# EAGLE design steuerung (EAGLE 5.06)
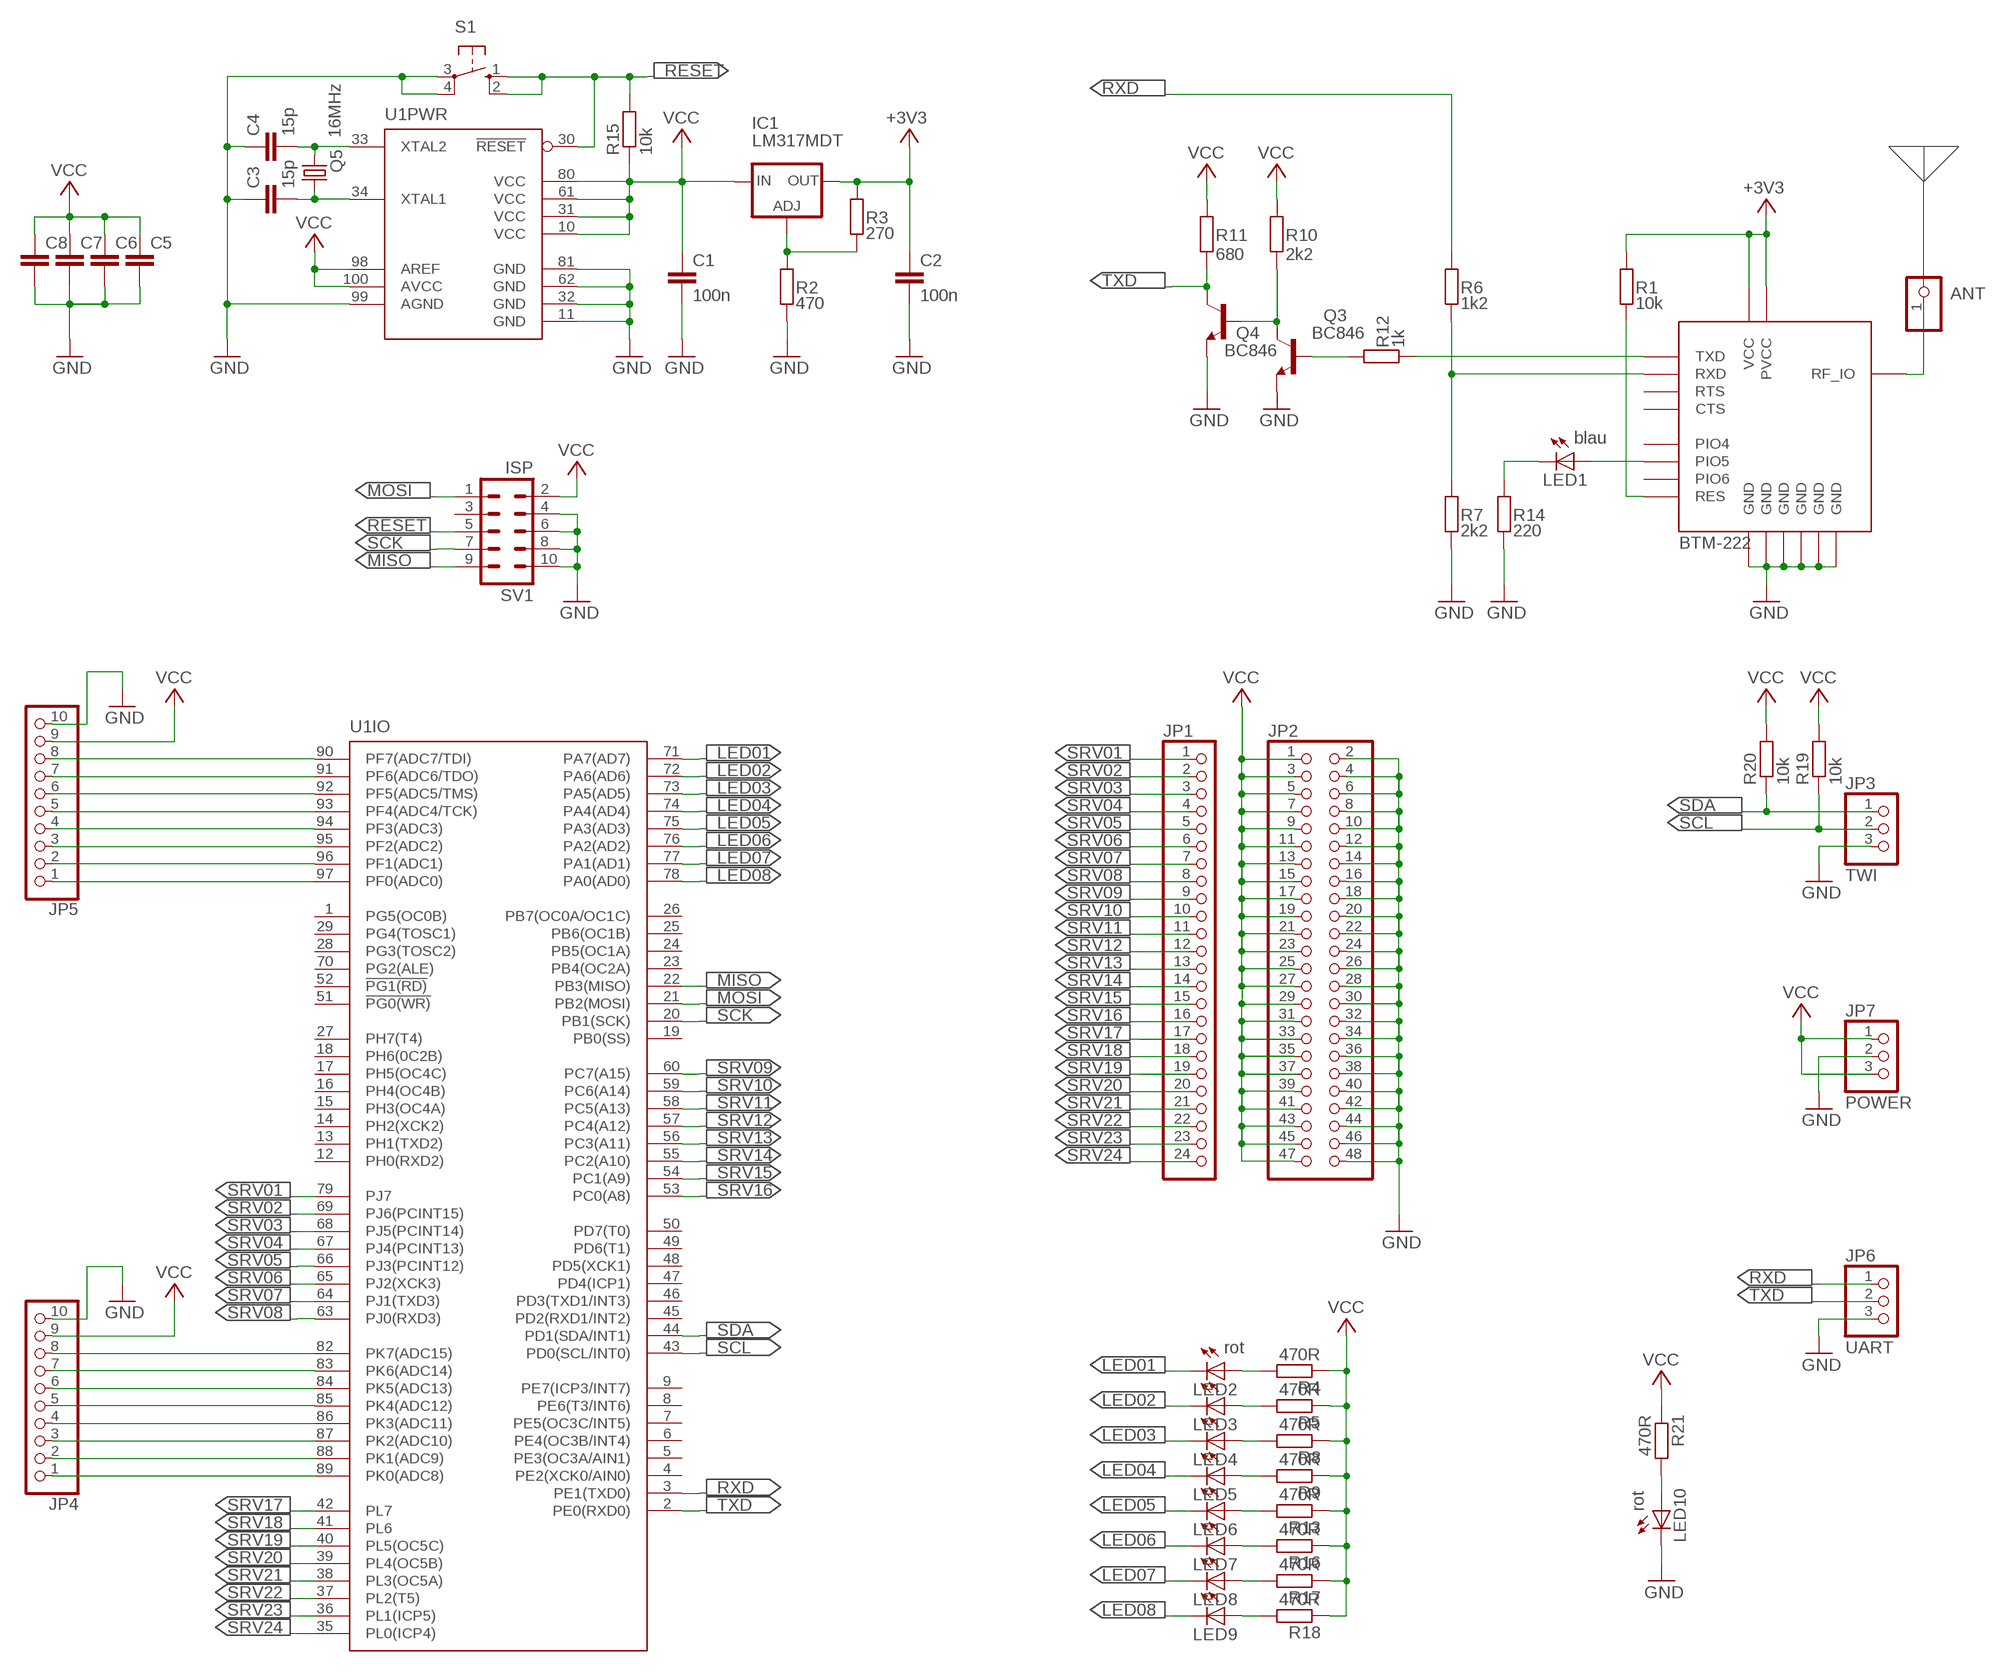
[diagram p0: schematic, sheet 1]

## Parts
ANT  PINHD-1X1  [1X01]
C1  100n  C-EUC0805  [C0805]
C2  100n  C-EUC0805  [C0805]
C3  15p  C-EUC0805  [C0805]
C4  15p  C-EUC0805  [C0805]
C5  C-EUC0805  [C0805]
C6  C-EUC0805  [C0805]
C7  C-EUC0805  [C0805]
C8  C-EUC0805  [C0805]
IC1  LM317MDT  [DPACK]
IC4  BTM_SER  [BTM_222]
JP1  PINHD-1X24  [1X24]
JP2  PINHD-2X24  [2X24]
JP3  TWI  PINHD-1X3  [1X03]
JP4  PINHD-1X10  [1X10]
JP5  PINHD-1X10  [1X10]
JP6  UART  PINHD-1X3  [1X03]
JP7  POWER  PINHD-1X3  [1X03]
LED1  LEDCHIP-LED0805  [CHIP-LED0805]
LED2  LEDCHIP-LED0805  [CHIP-LED0805]
LED3  LEDCHIP-LED0805  [CHIP-LED0805]
LED4  LEDCHIP-LED0805  [CHIP-LED0805]
LED5  LEDCHIP-LED0805  [CHIP-LED0805]
LED6  LEDCHIP-LED0805  [CHIP-LED0805]
LED7  LEDCHIP-LED0805  [CHIP-LED0805]
LED8  LEDCHIP-LED0805  [CHIP-LED0805]
LED9  LEDCHIP-LED0805  [CHIP-LED0805]
LED10  LEDCHIP-LED0805  [CHIP-LED0805]
Q3  BC846  BC846ALT1SMD  [SOT23]
Q4  BC846  BC846ALT1SMD  [SOT23]
Q5  16MHz  CRYSTALHC49U-V  [HC49U-V]
R1  10k  R-EU_M0805  [M0805]
R2  470  R-EU_M0805  [M0805]
R3  270  R-EU_M0805  [M0805]
R4  470R  R-EU_M0805  [M0805]
R5  470R  R-EU_M0805  [M0805]
R6  1k2  R-EU_M0805  [M0805]
R7  2k2  R-EU_M0805  [M0805]
R8  470R  R-EU_M0805  [M0805]
R9  470R  R-EU_M0805  [M0805]
R10  2k2  R-EU_M0805  [M0805]
R11  680  R-EU_M0805  [M0805]
R12  1k  R-EU_M0805  [M0805]
R13  470R  R-EU_M0805  [M0805]
R14  220  R-EU_M0805  [M0805]
R15  10k  R-EU_M0805  [M0805]
R16  470R  R-EU_M0805  [M0805]
R17  470R  R-EU_M0805  [M0805]
R18  470R  R-EU_M0805  [M0805]
R19  10k  R-EU_M0805  [M0805]
R20  10k  R-EU_M0805  [M0805]
R21  470R  R-EU_M0805  [M0805]
S1  10-XX  [B3F-10XX]
SV1  ISP  ML10  [ML10]
U1  ATMEGA640  [TQFP100]

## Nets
+3V3: C2.1 IC1.4(OUT) IC4.P$2(PVCC) IC4.P$17(VCC) R1.2 R3.2
GND: C1.2 C2.2 C3.1 C4.1 C5.2 C6.2 C7.2 C8.2 IC4.P$1(GND) IC4.P$10(GND) IC4.P$18(GND) IC4.P$19(GND) IC4.P$29(GND) IC4.P$38(GND) JP2.2 JP2.4 JP2.6 JP2.8 JP2.10 JP2.12 JP2.14 JP2.16 JP2.18 JP2.20 JP2.22 JP2.24 JP2.26 JP2.28 JP2.30 JP2.32 JP2.34 JP2.36 JP2.38 JP2.40 JP2.42 JP2.44 JP2.46 JP2.48 JP3.3 JP4.10 JP5.10 JP6.3 JP7.2 LED10.C Q3.2(E) Q4.2(E) R2.1 R7.1 R14.1 S1.3(P) S1.4(P1) SV1.4 SV1.6 SV1.8 SV1.10 U1.11(PWR:GND) U1.32(PWR:GND) U1.62(PWR:GND) U1.81(PWR:GND) U1.99(PWR:AGND)
LED01: LED2.C U1.71(IO:PA7(AD7))
LED02: LED3.C U1.72(IO:PA6(AD6))
LED03: LED4.C U1.73(IO:PA5(AD5))
LED04: LED5.C U1.74(IO:PA4(AD4))
LED05: LED6.C U1.75(IO:PA3(AD3))
LED06: LED7.C U1.76(IO:PA2(AD2))
LED07: LED8.C U1.77(IO:PA1(AD1))
LED08: LED9.C U1.78(IO:PA0(AD0))
MISO: SV1.9 U1.22(IO:PB3(MISO))
MOSI: SV1.1 U1.21(IO:PB2(MOSI))
N$1: LED2.A R4.2
N$2: IC1.1(ADJ) R2.2 R3.1
N$3: IC4.P$27(TXD) R12.1
N$4: LED3.A R5.2
N$5: IC4.P$26(RXD) R6.1 R7.2
N$6: ANT.1 IC4.P$37(RF_IO)
N$7: C3.2 Q5.1 U1.34(PWR:XTAL1)
N$8: LED4.A R8.2
N$9: Q3.3(C) Q4.1(B) R10.2
N$10: IC4.P$11(PIO5) LED1.A
N$11: LED5.A R9.2
N$12: Q3.1(B) R12.2
N$13: LED1.C R14.2
N$14: LED6.A R13.2
N$15: C4.2 Q5.2 U1.33(PWR:XTAL2)
N$16: LED7.A R16.2
N$17: LED8.A R17.2
N$18: LED9.A R18.2
N$19: JP5.1 U1.97(IO:PF0(ADC0))
N$20: JP5.2 U1.96(IO:PF1(ADC1))
N$21: JP5.3 U1.95(IO:PF2(ADC2))
N$22: JP5.4 U1.94(IO:PF3(ADC3))
N$23: IC4.P$16(RES) R1.1
N$24: JP5.5 U1.93(IO:PF4(ADC4/TCK))
N$25: JP5.6 U1.92(IO:PF5(ADC5/TMS))
N$26: JP5.7 U1.91(IO:PF6(ADC6/TDO))
N$27: JP5.8 U1.90(IO:PF7(ADC7/TDI))
N$28: JP4.1 U1.89(IO:PK0(ADC8))
N$29: JP4.2 U1.88(IO:PK1(ADC9))
N$30: JP4.3 U1.87(IO:PK2(ADC10))
N$31: JP4.4 U1.86(IO:PK3(ADC11))
N$32: JP4.5 U1.85(IO:PK4(ADC12))
N$33: JP4.6 U1.84(IO:PK5(ADC13))
N$34: JP4.7 U1.83(IO:PK6(ADC14))
N$35: JP4.8 U1.82(IO:PK7(ADC15))
N$36: LED10.A R21.2
RESET: R15.2 S1.1(S) S1.2(S1) SV1.5 U1.30(PWR:!RESET)
RXD: JP6.1 R6.2 U1.3(IO:PE1(TXD0))
SCK: SV1.7 U1.20(IO:PB1(SCK))
SCL: JP3.2 R19.1 U1.43(IO:PD0(SCL/INT0))
SDA: JP3.1 R20.1 U1.44(IO:PD1(SDA/INT1))
SRV01: JP1.1 U1.79(IO:PJ7)
SRV02: JP1.2 U1.69(IO:PJ6(PCINT15))
SRV03: JP1.3 U1.68(IO:PJ5(PCINT14))
SRV04: JP1.4 U1.67(IO:PJ4(PCINT13))
SRV05: JP1.5 U1.66(IO:PJ3(PCINT12))
SRV06: JP1.6 U1.65(IO:PJ2(XCK3))
SRV07: JP1.7 U1.64(IO:PJ1(TXD3))
SRV08: JP1.8 U1.63(IO:PJ0(RXD3))
SRV09: JP1.9 U1.60(IO:PC7(A15))
SRV10: JP1.10 U1.59(IO:PC6(A14))
SRV11: JP1.11 U1.58(IO:PC5(A13))
SRV12: JP1.12 U1.57(IO:PC4(A12))
SRV13: JP1.13 U1.56(IO:PC3(A11))
SRV14: JP1.14 U1.55(IO:PC2(A10))
SRV15: JP1.15 U1.54(IO:PC1(A9))
SRV16: JP1.16 U1.53(IO:PC0(A8))
SRV17: JP1.17 U1.42(IO:PL7)
SRV18: JP1.18 U1.41(IO:PL6)
SRV19: JP1.19 U1.40(IO:PL5(OC5C))
SRV20: JP1.20 U1.39(IO:PL4(OC5B))
SRV21: JP1.21 U1.38(IO:PL3(OC5A))
SRV22: JP1.22 U1.37(IO:PL2(T5))
SRV23: JP1.23 U1.36(IO:PL1(ICP5))
SRV24: JP1.24 U1.35(IO:PL0(ICP4))
TXD: JP6.2 Q4.3(C) R11.2 U1.2(IO:PE0(RXD0))
VCC: C1.1 C5.1 C6.1 C7.1 C8.1 IC1.3(IN) JP2.1 JP2.3 JP2.5 JP2.7 JP2.9 JP2.11 JP2.13 JP2.15 JP2.17 JP2.19 JP2.21 JP2.23 JP2.25 JP2.27 JP2.29 JP2.31 JP2.33 JP2.35 JP2.37 JP2.39 JP2.41 JP2.43 JP2.45 JP2.47 JP4.9 JP5.9 JP7.1 JP7.3 R4.1 R5.1 R8.1 R9.1 R10.1 R11.1 R13.1 R15.1 R16.1 R17.1 R18.1 R19.2 R20.2 R21.1 SV1.2 U1.10(PWR:VCC) U1.31(PWR:VCC) U1.61(PWR:VCC) U1.80(PWR:VCC) U1.98(PWR:AREF) U1.100(PWR:AVCC)
Unconnected: IC4.P$9(PIO4) IC4.P$12(PIO6) IC4.P$28(RTS) IC4.P$30(CTS) SV1.3 U1.1(IO:PG5(OC0B)) U1.4(IO:PE2(XCK0/AIN0)) U1.5(IO:PE3(OC3A/AIN1)) U1.6(IO:PE4(OC3B/INT4)) U1.7(IO:PE5(OC3C/INT5)) U1.8(IO:PE6(T3/INT6)) U1.9(IO:PE7(ICP3/INT7)) U1.12(IO:PH0(RXD2)) U1.13(IO:PH1(TXD2)) U1.14(IO:PH2(XCK2)) U1.15(IO:PH3(OC4A)) U1.16(IO:PH4(OC4B)) U1.17(IO:PH5(OC4C)) U1.18(IO:PH6(0C2B)) U1.19(IO:PB0(SS)) U1.23(IO:PB4(OC2A)) U1.24(IO:PB5(OC1A)) U1.25(IO:PB6(OC1B)) U1.26(IO:PB7(OC0A/OC1C)) U1.27(IO:PH7(T4)) U1.28(IO:PG3(TOSC2)) U1.29(IO:PG4(TOSC1)) U1.45(IO:PD2(RXD1/INT2)) U1.46(IO:PD3(TXD1/INT3)) U1.47(IO:PD4(ICP1)) U1.48(IO:PD5(XCK1)) U1.49(IO:PD6(T1)) U1.50(IO:PD7(T0)) U1.51(IO:!PG0(WR)) U1.52(IO:!PG1(RD)) U1.70(IO:PG2(ALE))

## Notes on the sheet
- 680 | 2k2
- blau
- BTM-222
- rot
- rot

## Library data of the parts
ANT = pinhead:PINHD-1X1: PIN HEADER
C1 C2 = rcl:C-EU: CAPACITOR, European symbol
C3-C8 = resistor:C-EU: CAPACITOR, European symbol
IC1 = v-reg:LM317?*: 500 mA Adjustable Output Positive Voltage Regulator Source: http://www.onsemi.co.jp .. LM317M-D.PDF
IC4 = BTM222:BTM_SER
JP1 = pinhead:PINHD-1X24: PIN HEADER
JP2 = pinhead:PINHD-2X24: PIN HEADER
JP3 JP6 JP7 = pinhead:PINHD-1X3: PIN HEADER
JP4 JP5 = pinhead:PINHD-1X10: PIN HEADER
LED1-LED10 = led:LED: LED
Q3 Q4 = transistor-npn:BC846*: NPN Transistor
Q5 = crystal:CRYSTAL: CRYSTAL
R1-R3 R6 R7 R10-R12 R14 = rcl:R-EU_: RESISTOR, European symbol
R4 R5 R8 R9 R13 R15-R21 = resistor:R-EU_: RESISTOR, European symbol
S1 = switch-omron:10-XX: OMRON SWITCH
SV1 = con-harting-ml:ML10: HARTING
U1 = ATmega640:ATMEGA640

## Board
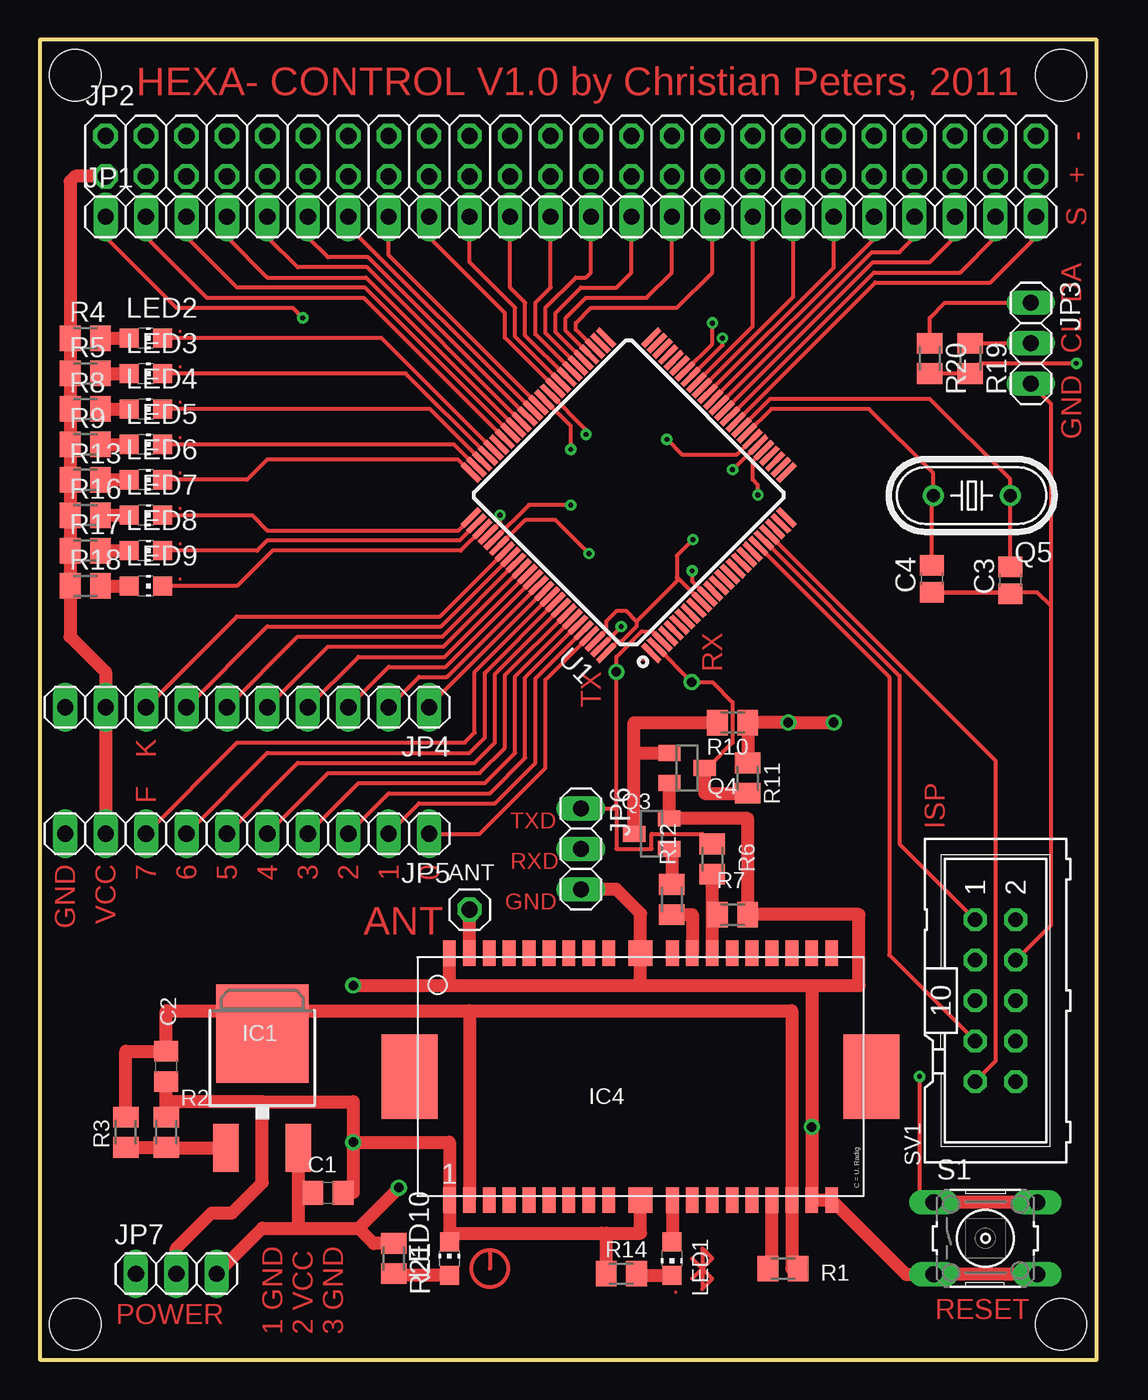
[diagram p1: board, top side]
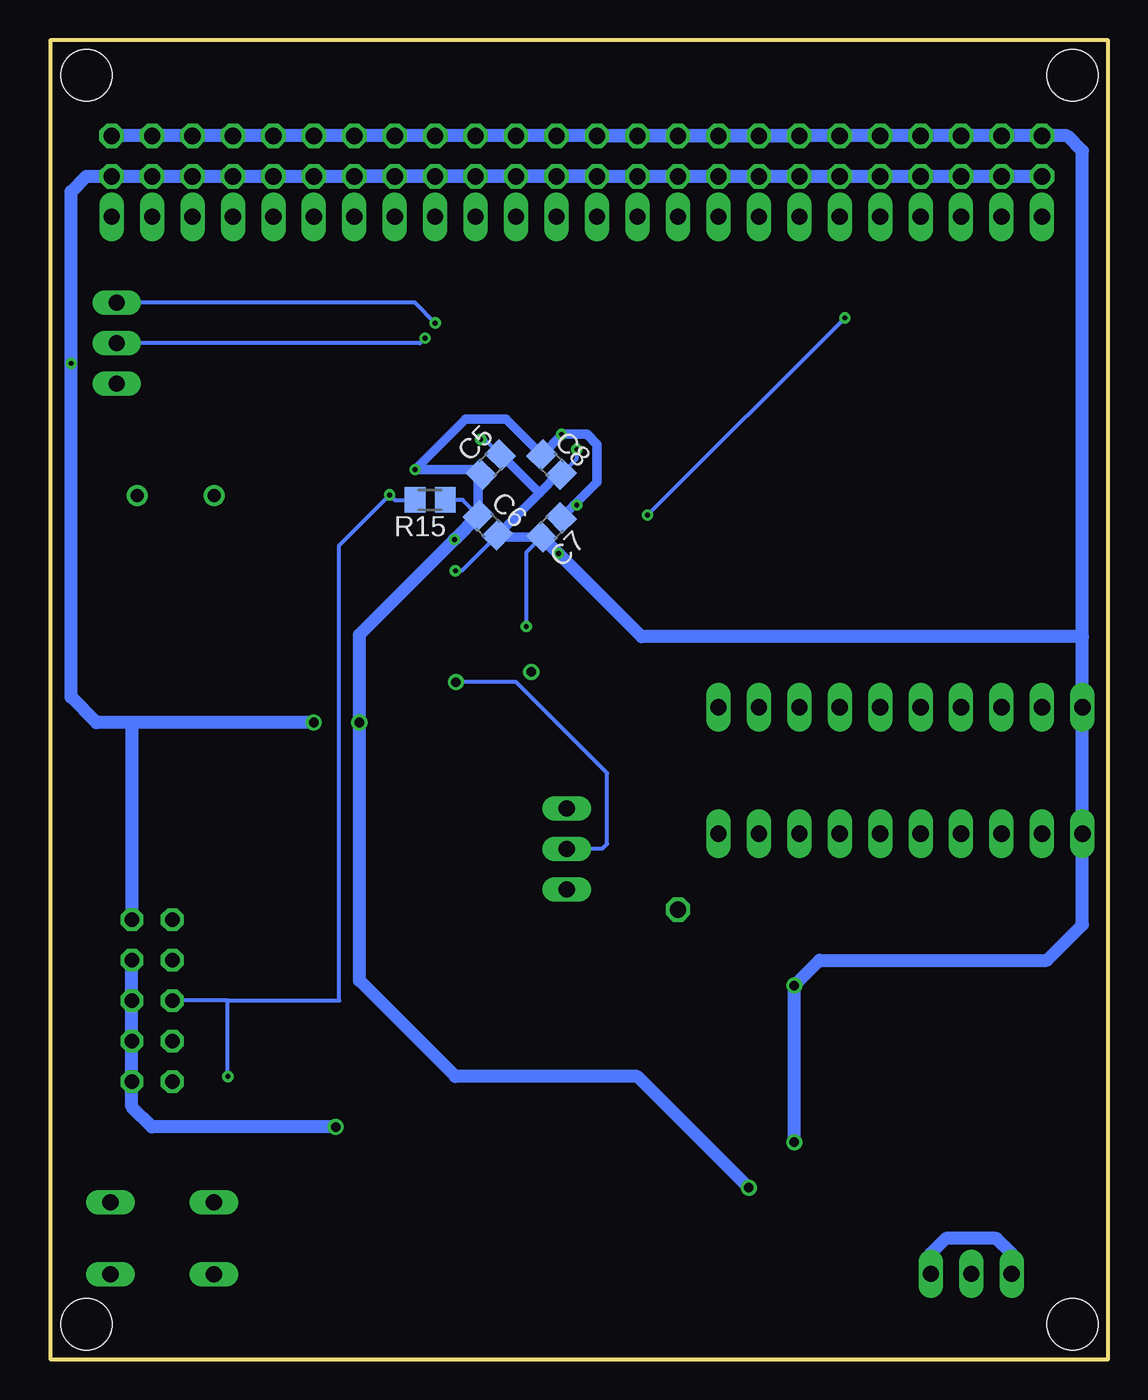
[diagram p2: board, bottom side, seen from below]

Size 66.36 x 82.87 mm. Coordinates in mm from the lower left corner, seen from the top.
Outline: 0,0 66.36,0 66.36,82.87 0,82.87 0,0
Copper layers (1*16): Top 0.035mm / dielectric 1.5mm / Bottom 0.035mm
Design rules "default": minimum track width 10mil, minimum drill 24mil, track to track 8mil, track to pad 8mil, pad to pad 8mil, via to via 8mil, smd to smd 8mil, copper to edge 40mil, drill to drill 8mil, minimum pad ring 10mil, minimum via ring 8mil, stop-mask expansion 4mil, vias tented up to drill 0mil, thermal gap 10mil
Holes 3.2 mm at 2.22,80.65 64.14,80.65 2.22,2.22 64.14,2.22

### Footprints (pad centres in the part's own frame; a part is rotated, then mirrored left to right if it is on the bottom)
1X01 = drill 1.016 octagon: 1 0,0
C0805 = smd 1.3 x 1.5: 1 -0.95,0; 2 0.95,0
C0805' = smd 1.3 x 1.5: 1 -0.85,0; 2 0.85,0
DPACK = smd 1.6 x 3: 1 -2.28,-4.8; 3 2.28,-4.8 | smd 5.8 x 6.2: 4 0,2.38
BTM_222 = smd 0.8 x 1.6: P$1 -11.43,-7.75; P$2 -10.18,-7.75; P$3 -8.93,-7.75; P$4 -7.68,-7.75; P$5 -6.43,-7.75; P$6 -5.18,-7.75; P$7 -3.93,-7.75; P$8 -2.68,-7.75; P$9 -1.43,-7.75; P$11 2.57,-7.75; P$12 3.82,-7.75; P$13 5.07,-7.75; P$14 6.32,-7.75; P$15 7.57,-7.75; P$16 8.82,-7.75; P$17 10.07,-7.75; P$18 11.32,-7.75; P$19 12.57,-7.75; P$20 12.57,7.75; P$21 11.32,7.75; P$22 10.07,7.75; P$23 8.82,7.75; P$24 7.57,7.75; P$25 6.32,7.75; P$26 5.07,7.75; P$27 3.82,7.75; P$28 2.57,7.75; P$30 -1.43,7.75; P$31 -2.68,7.75; P$32 -3.93,7.75; P$33 -5.18,7.75; P$34 -6.43,7.75; P$35 -7.68,7.75; P$36 -8.93,7.75; P$37 -10.18,7.75; P$38 -11.43,7.75 | smd 1.5 x 1.6: P$10 0.57,-7.75; P$29 0.57,7.75 | smd 3.5 x 5.3: P$39 -13.93,0; P$40 15.07,0
1X24 = drill 1.016 long: 1 -29.21,0; 2 -26.67,0; 3 -24.13,0; 4 -21.59,0; 5 -19.05,0; 6 -16.51,0; 7 -13.97,0; 8 -11.43,0; 9 -8.89,0; 10 -6.35,0; 11 -3.81,0; 12 -1.27,0; 13 1.27,0; 14 3.81,0; 15 6.35,0; 16 8.89,0; 17 11.43,0; 18 13.97,0; 19 16.51,0; 20 19.05,0; 21 21.59,0; 22 24.13,0; 23 26.67,0; 24 29.21,0
2X24 = drill 1.016 octagon: 1 -27.94,-1.27; 2 -27.94,1.27; 3 -25.4,-1.27; 4 -25.4,1.27; 5 -22.86,-1.27; 6 -22.86,1.27; 7 -20.32,-1.27; 8 -20.32,1.27; 9 -17.78,-1.27; 10 -17.78,1.27; 11 -15.24,-1.27; 12 -15.24,1.27; 13 -12.7,-1.27; 14 -12.7,1.27; 15 -10.16,-1.27; 16 -10.16,1.27; 17 -7.62,-1.27; 18 -7.62,1.27; 19 -5.08,-1.27; 20 -5.08,1.27; 21 -2.54,-1.27; 22 -2.54,1.27; 23 0,-1.27; 24 0,1.27; 25 2.54,-1.27; 26 2.54,1.27; 27 5.08,-1.27; 28 5.08,1.27; 29 7.62,-1.27; 30 7.62,1.27; 31 10.16,-1.27; 32 10.16,1.27; 33 12.7,-1.27; 34 12.7,1.27; 35 15.24,-1.27; 36 15.24,1.27; 37 17.78,-1.27; 38 17.78,1.27; 39 20.32,-1.27; 40 20.32,1.27; 41 22.86,-1.27; 42 22.86,1.27; 43 25.4,-1.27; 44 25.4,1.27; 45 27.94,-1.27; 46 27.94,1.27; 47 30.48,-1.27; 48 30.48,1.27
1X03 = drill 1.016 long: 1 -2.54,0; 2 0,0; 3 2.54,0
1X10 = drill 1.016 long: 1 -11.43,0; 2 -8.89,0; 3 -6.35,0; 4 -3.81,0; 5 -1.27,0; 6 1.27,0; 7 3.81,0; 8 6.35,0; 9 8.89,0; 10 11.43,0
CHIP-LED0805 = smd 1.2 x 1.2: A 0,-1.05; C 0,1.05
SOT23 = smd 1 x 1.4: 1 -0.95,-1.1; 2 0.95,-1.1; 3 0,1.1
HC49U-V = drill 0.813 round: 1 -2.413,0; 2 2.413,0
M0805 = smd 1.3 x 1.6: 1 -0.95,0; 2 0.95,0
B3F-10XX = drill 1.016 long: 1 -3.251,2.261; 2 3.251,2.261; 3 -3.251,-2.261; 4 3.251,-2.261
ML10 = drill 0.914 octagon: 1 -5.08,-1.27; 2 -5.08,1.27; 3 -2.54,-1.27; 4 -2.54,1.27; 5 0,-1.27; 6 0,1.27; 7 2.54,-1.27; 8 2.54,1.27; 9 5.08,-1.27; 10 5.08,1.27
TQFP100 = smd 1.5 x 0.35: 1 -8,6; 2 -8,5.5; 3 -8,5; 4 -8,4.5; 5 -8,4; 6 -8,3.5; 7 -8,3; 8 -8,2.5; 9 -8,2; 10 -8,1.5; 11 -8,1; 12 -8,0.5; 13 -8,0; 14 -8,-0.5; 15 -8,-1; 16 -8,-1.5; 17 -8,-2; 18 -8,-2.5; 19 -8,-3; 20 -8,-3.5; 21 -8,-4; 22 -8,-4.5; 23 -8,-5; 24 -8,-5.5; 25 -8,-6; 51 8,-6; 52 8,-5.5; 53 8,-5; 54 8,-4.5; 55 8,-4; 56 8,-3.5; 57 8,-3; 58 8,-2.5; 59 8,-2; 60 8,-1.5; 61 8,-1; 62 8,-0.5; 63 8,0; 64 8,0.5; 65 8,1; 66 8,1.5; 67 8,2; 68 8,2.5; 69 8,3; 70 8,3.5; 71 8,4; 72 8,4.5; 73 8,5; 74 8,5.5; 75 8,6 | smd 0.35 x 1.5: 26 -6,-8; 27 -5.5,-8; 28 -5,-8; 29 -4.5,-8; 30 -4,-8; 31 -3.5,-8; 32 -3,-8; 33 -2.5,-8; 34 -2,-8; 35 -1.5,-8; 36 -1,-8; 37 -0.5,-8; 38 0,-8; 39 0.5,-8; 40 1,-8; 41 1.5,-8; 42 2,-8; 43 2.5,-8; 44 3,-8; 45 3.5,-8; 46 4,-8; 47 4.5,-8; 48 5,-8; 49 5.5,-8; 50 6,-8; 76 6,8; 77 5.5,8; 78 5,8; 79 4.5,8; 80 4,8; 81 3.5,8; 82 3,8; 83 2.5,8; 84 2,8; 85 1.5,8; 86 1,8; 87 0.5,8; 88 0,8; 89 -0.5,8; 90 -1,8; 91 -1.5,8; 92 -2,8; 93 -2.5,8; 94 -3,8; 95 -3.5,8; 96 -4,8; 97 -4.5,8; 98 -5,8; 99 -5.5,8; 100 -6,8

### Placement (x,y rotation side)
ANT  26.99,28.26 0 top
C1  18.1,10.48 0 top
C2  7.94,18.42 270 top
C3  15p  [C0805']  60.94,48.93 90 top
C4  15p  [C0805']  56.01,49.03 90 top
C5  [C0805']  38.73,56.2 45 bottom
C6  [C0805']  38.92,52.39 315 bottom
C7  [C0805']  34.92,52.26 225 bottom
C8  [C0805']  34.92,56.2 315 bottom
IC1  13.97,18.1 0 top
IC4  37.15,17.78 0 top
JP1  33.34,71.76 0 top
JP2  32.07,75.57 0 top
JP3  62.23,63.82 270 top
JP4  13.02,40.96 180 top
JP5  13.02,33.02 180 top
JP6  33.97,32.07 270 top
JP7  8.57,5.4 0 top
LED1  39.69,6.35 180 top
LED2  6.67,64.14 270 top
LED3  6.67,61.91 270 top
LED4  6.67,59.69 270 top
LED5  6.67,57.47 270 top
LED6  6.67,55.25 270 top
LED7  6.67,53.02 270 top
LED8  6.67,50.8 270 top
LED9  6.67,48.58 270 top
LED10  25.72,6.35 0 top
Q3  38.42,33.02 90 top
Q4  40.64,37.15 270 top
Q5  58.51,54.25 180 top
R1  46.67,5.72 0 top
R2  7.94,14.29 270 top
R3  5.4,14.29 90 top
R4  2.86,64.14 0 top
R5  2.86,61.91 0 top
R6  42.23,31.43 90 top
R7  43.5,27.94 180 top
R8  2.86,59.69 0 top
R9  2.86,57.47 0 top
R10  43.5,40.01 180 top
R11  44.45,36.51 270 top
R12  39.69,28.89 90 top
R13  2.86,55.25 0 top
R14  36.51,5.4 0 top
R15  42.55,53.98 180 bottom
R16  2.86,53.02 0 top
R17  2.86,50.8 0 top
R18  2.86,48.58 0 top
R19  58.42,62.87 270 top
R20  55.88,62.87 270 top
R21  22.23,6.35 270 top
S1  59.37,7.62 0 top
SV1  60.01,22.54 270 top
U1  36.98,54.28 135 top

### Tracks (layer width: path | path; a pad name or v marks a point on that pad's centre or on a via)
+3V3
  Top 0.813: 13.97,21.91 IC1.4 | 13.97,21.91 26.97,21.91 | 26.97,21.91 IC4.P$2 | 26.97,21.91 47.22,21.91 IC4.P$17 47.22,5.71 R1.2 | 13.97,21.91 7.94,21.91 C2.1 5.4,19.37 R3.2
GND  (via drill 0.3, 0.3 pad 0.61, 0.6)
  Top 0.254: U1.81 30.46,52.7 32.38,52.7 v34.48,50.61 | v33.34,57.15 33.34,58.62 U1.62 | v39.37,57.79 40.32,56.83 43.78,56.83 U1.32 | v40.96,49.53 40.96,48.88 U1.11 | U1.99 36.2,45.72 v36.51,46.04 | C3.1 60.85,48.18 C4.1 62.63,48.18 63.5,47.31 | 63.5,47.31 63.5,27.31 SV1.4 | JP3.3 63.5,60.01 63.5,47.31
  Top 0.813: 25.72,23.49 IC4.P$38 | 25.72,23.49 37.72,23.49 | 37.72,23.49 IC4.P$29 37.72,28.01 36.2,29.53 JP6.3 | 37.72,23.49 48.47,23.49 | 25.72,7.94 IC4.P$1 25.72,13.65 v19.68,13.65 | 25.72,7.94 35.24,7.94 | 35.24,7.94 37.72,7.94 IC4.P$10 | v19.68,23.49 25.72,23.49 | R14.1 35.56,7.94 35.24,7.94 | C2.2 R2.1 7.94,16.19 13.97,16.19 | 13.97,16.19 19.68,16.19 v19.68,13.65 | C1.2 19.68,10.48 v19.68,13.65 | 48.47,23.49 51.44,23.49 51.44,27.94 R7.1 44.45,33.97 39.54,33.97 | 39.54,33.97 Q3.2 | 39.54,33.97 Q4.2 | 48.47,23.49 v48.47,14.6 IC4.P$18 IC4.P$19 54.39,5.36 S1.3 S1.4 | JP7.2 8.57,6.99 10.79,9.21 12.06,9.21 13.97,11.11 13.97,16.19 | 25.72,7.94 LED10.C
  Bottom 0.254: C8.2 33.34,56.58 v33.34,57.15 | C5.2 39.12,57.79 v39.37,57.79 | 38.32,51.53 C6.2 40.58,49.53 v40.96,49.53 | v36.51,46.04 36.51,50.67 C7.2 v34.48,50.61
  Bottom 0.61: C7.2 38.19,51.65 C6.2 35.69,54.42 | C8.2 34.51,55.6 35.69,54.42 | C5.2 38.07,56.8 35.69,54.42
  Bottom 0.813: v19.68,13.65 v19.68,23.49 18.1,25.08 3.81,25.08 1.59,27.31 JP5.10 | C7.2 v34.48,50.61 29.27,45.4 1.59,45.4 JP4.10 | SV1.4 SV1.6 SV1.8 SV1.10 61.28,15.87 60.01,14.6 v48.47,14.6 | JP2.2 JP2.4 JP2.6 JP2.8 JP2.10 JP2.12 JP2.14 JP2.16 JP2.18 JP2.20 JP2.22 JP2.24 | JP2.24 JP2.26 JP2.28 JP2.30 JP2.32 JP2.34 JP2.36 JP2.38 JP2.40 JP2.42 JP2.44 JP2.46 JP2.48 | JP2.2 JP2.24 | JP2.2 2.54,76.84 1.59,75.88 JP4.10 | JP5.10 JP4.10 | JP5.10 JP4.10
LED01
  Top 0.254: U1.71 21.46,64.13 LED2.C
LED02
  Top 0.254: U1.72 22.98,61.91 LED3.C
LED03
  Top 0.254: U1.73 24.49,59.69 LED4.C
LED04
  Top 0.254: U1.74 26.01,57.47 LED5.C
LED05
  Top 0.254: U1.75 26.25,56.52 14.29,56.52 13.02,55.25 LED6.C
LED06
  Top 0.254: U1.76 26.29,52.07 14.29,52.07 13.34,53.02 LED7.C
LED07
  Top 0.254: U1.77 26.36,51.43 14.29,51.43 13.65,50.8 LED8.C
LED08
  Top 0.254: U1.78 26.43,50.8 14.61,50.8 12.38,48.58 LED9.C
MISO
  Top 0.254: U1.22 60.01,37.61 60.01,18.73 SV1.9
MOSI
  Top 0.254: U1.21 53.98,42.94 53.98,32.38 SV1.1
N$1
  Top 0.813: R4.2 LED2.A
N$2
  Top 0.813: IC1.1 7.94,13.3 R2.2 R3.1
N$3
  Top 0.813: R12.1 40.97,27.94 IC4.P$27
N$4
  Top 0.813: R5.2 LED3.A
N$5
  Top 0.813: IC4.P$26 42.23,27.94 | 42.23,27.94 R6.1 | 42.23,27.94 R7.2 | 42.23,27.94
N$6
  Top 0.813: IC4.P$37 26.97,26.35 ANT.1
N$7
  Top 0.254: C3.2 60.94,54.24 Q5.1 60.93,55.28 55.88,60.32 45.85,60.32 U1.34
N$8
  Top 0.813: R8.2 LED4.A
N$9
  Top 0.813: Q3.3 37.32,38.1 | 37.32,38.1 Q4.1 | R10.2 37.32,40.01 37.32,38.1
N$10
  Top 0.813: IC4.P$11 39.72,7.4 LED1.A
N$11
  Top 0.813: R9.2 LED5.A
N$12
  Top 0.813: Q3.1 39.69,32.07 R12.2
N$13
  Top 0.813: R14.2 37.46,5.3 LED1.C
N$14
  Top 0.813: R13.2 LED6.A
N$15
  Top 0.254: C4.2 56.01,54.17 Q5.2 56.1,55.66 52.07,59.69 45.93,59.69 U1.33
N$16
  Top 0.813: R16.2 LED7.A
N$17
  Top 0.813: R17.2 LED8.A
N$18
  Top 0.813: R18.2 LED9.A
N$19
  Top 0.254: JP5.1 27.62,33.02 31.75,37.15 31.75,42.69 U1.97
N$20
  Top 0.254: JP5.2 23.81,34.92 28.57,34.92 31.11,37.46 31.11,42.76 U1.96
N$21
  Top 0.254: JP5.3 21.91,35.56 28.26,35.56 30.48,37.78 30.48,42.83 U1.95
N$22
  Top 0.254: JP5.4 20,36.2 27.94,36.2 29.84,38.1 29.84,42.9 U1.94
N$23
  Top 0.813: R1.1 45.97,5.71 IC4.P$16
N$24
  Top 0.254: JP5.5 18.1,36.83 27.62,36.83 29.21,38.42 29.21,42.97 U1.93
N$25
  Top 0.254: JP5.6 16.19,37.46 27.3,37.46 28.57,38.73 28.57,43.05 U1.92
N$26
  Top 0.254: JP5.7 14.29,38.1 26.99,38.1 27.94,39.05 27.94,43.12 U1.91
N$27
  Top 0.254: JP5.8 12.38,38.73 26.67,38.73 27.3,39.37 27.3,43.19 U1.90
N$28
  Top 0.254: JP4.1 24.45,41.04 U1.89
N$29
  Top 0.254: JP4.2 23.81,42.86 25.56,42.86 U1.88
N$30
  Top 0.254: JP4.3 21.91,43.5 25.49,43.5 U1.87
N$31
  Top 0.254: JP4.4 20,44.13 25.42,44.13 U1.86
N$32
  Top 0.254: JP4.5 18.1,44.77 25.35,44.77 U1.85
N$33
  Top 0.254: JP4.6 16.19,45.4 25.27,45.4 U1.84
N$34
  Top 0.254: JP4.7 14.29,46.04 25.2,46.04 U1.83
N$35
  Top 0.254: JP4.8 12.38,46.67 25.13,46.67 U1.82
N$36
  Top 0.813: LED10.A 22.32,5.3 R21.2
N$37
  Top 0.254: 28.26,6.67 28.26,5.71
N$38
  Top 0.254: 40.96,6.35 42.23,5.08 41.59,4.45 41.59,6.99 42.23,6.35 40.96,5.08
RESET  (via drill 0.3)
  Top 0.254: v45.09,54.29 45.09,54.93 44.77,55.25 44.77,56.41 U1.30 | v55.24,17.78 55.24,9.88 S1.1
  Top 0.813: S1.2 S1.1
  Bottom 0.254: R15.2 44.77,53.98 v45.09,54.29 48.26,51.12 48.26,22.54 55.24,22.54 | v55.24,17.78 55.24,22.54 | 55.24,22.54 SV1.5
RXD  (via drill 0.6)
  Top 0.254: R6.2 41.59,33.02 38.42,33.02 38.42,32.07 36.2,32.07 36.2,34.61 | 36.2,34.61 v36.2,43.18 36.2,44.13 37.78,45.72 38.46,45.72 U1.3 | JP6.1 36.2,34.61
SCK
  Top 0.254: U1.20 53.34,42.86 53.34,25.4 SV1.7
SCL  (via drill 0.3)
  Top 0.254: U1.43 42.86,63.7 v42.86,64.13 | R19.1 JP3.2
  Bottom 0.254: v42.86,64.13 43.18,63.82 JP3.2
SDA  (via drill 0.3)
  Top 0.254: U1.44 42.23,63.77 v42.23,65.09 | R20.1 55.88,65.41 56.83,66.36 JP3.1
  Bottom 0.254: v42.23,65.09 43.5,66.36 JP3.1
SRV01  (via drill 0.3)
  Top 0.254: JP1.1 4.13,70.48 8.57,66.04 15.88,66.04 v16.51,65.41 | U1.79 28.89,52.56 v28.89,53.02
  Bottom 0.254: v16.51,65.41 v28.89,53.02
SRV02
  Top 0.254: U1.69 20.34,66.68 10.48,66.68 6.67,70.48 JP1.2
SRV03
  Top 0.254: U1.68 20.41,67.31 12.38,67.31 9.21,70.48 JP1.3
SRV04
  Top 0.254: U1.67 20.48,67.95 14.29,67.95 11.75,70.48 JP1.4
SRV05
  Top 0.254: U1.66 20.55,68.58 16.19,68.58 14.29,70.48 JP1.5
SRV06
  Top 0.254: U1.65 20.62,69.22 18.1,69.22 16.83,70.48 JP1.6
SRV07
  Top 0.254: U1.64 19.37,71.18 JP1.7
SRV08
  Top 0.254: U1.63 21.91,69.35 JP1.8
SRV09
  Top 0.254: U1.60 29.21,64.17 29.21,65.72 24.45,70.48 JP1.9
SRV10
  Top 0.254: U1.59 29.84,64.24 29.84,66.04 26.99,68.9 JP1.10
SRV11
  Top 0.254: U1.58 30.48,64.31 30.48,66.36 29.53,67.31 JP1.11
SRV12
  Top 0.254: U1.57 31.11,64.38 31.11,66.36 32.07,67.31 JP1.12
SRV13
  Top 0.254: U1.56 31.75,64.45 31.75,66.04 33.66,67.95 34.29,67.95 34.61,68.26 JP1.13
SRV14
  Top 0.254: U1.55 32.38,64.53 32.38,65.72 33.97,67.31 36.2,67.31 37.15,68.26 JP1.14
SRV15
  Top 0.254: U1.54 33.02,64.6 33.02,65.41 34.29,66.68 38.1,66.68 39.69,68.26 JP1.15
SRV16
  Top 0.254: U1.53 33.66,64.67 33.66,65.09 34.61,66.04 40.01,66.04 42.23,68.26 JP1.16
SRV17
  Top 0.254: U1.42 44.77,64.9 JP1.17
SRV18
  Top 0.254: U1.41 47.31,66.73 JP1.18
SRV19
  Top 0.254: U1.40 49.85,68.56 JP1.19
SRV20
  Top 0.254: U1.39 52.39,70.39 JP1.20
SRV21
  Top 0.254: U1.38 52.23,69.53 53.98,69.53 54.93,70.48 JP1.21
SRV22
  Top 0.254: U1.37 52.3,68.9 55.88,68.9 57.47,70.48 JP1.22
SRV23
  Top 0.254: U1.36 52.38,68.26 57.78,68.26 60.01,70.48 JP1.23
SRV24
  Top 0.254: U1.35 52.45,67.63 59.69,67.63 62.55,70.48 JP1.24
TXD  (via drill 0.6)
  Top 0.254: U1.2 v40.93,42.55 42.23,42.55 43.5,41.27 43.5,38.73 41.91,37.15 Q4.3
  Top 0.813: Q4.3 41.74,35.56 R11.2
  Bottom 0.254: JP6.2 31.75,32.07 31.43,32.38 31.43,36.83 37.15,42.55 v40.93,42.55
VCC  (via drill 0.3, 0.3 pad 0.61, 0.6)
  Top 0.254: v33.34,53.66 30.7,53.66 U1.80 | v34.29,58.1 34.29,58.38 U1.61 | v43.5,55.88 43.53,55.88 U1.31 | 40.01,49.13 U1.10 | U1.98 35.56,45.79 35.56,46.35 36.2,46.99 36.83,46.99 37.47,46.35 | 37.47,46.35 37.47,46.04 36.51,45.09 36.27,45.09 U1.100 | 40.01,49.13 40.01,48.9 37.47,46.35 | 40.01,49.13 40.01,50.48 v41.02,51.49 | R20.2 R19.2 59.05,62.55 v65.09,62.55
  Top 0.813: 16.25,10.48 C1.1 | 16.25,10.48 IC1.3 | R11.1 R10.1 v46.99,40.01 v49.85,40.01 | 16.25,8.26 16.25,10.48 | 16.25,8.26 20,8.26 | 20,8.26 v22.54,10.79 | JP2.1 2.22,74.3 1.91,73.98 R4.1 R5.1 R8.1 R9.1 R13.1 R16.1 R17.1 R18.1 1.91,45.4 4.13,43.18 JP4.9 JP5.9 | JP7.3 13.97,8.26 16.25,8.26 | R21.1 20.96,7.3 20,8.26
  Bottom 0.254: C7.1 34.14,52.86 | C8.1 35.53,56.87 | R15.1 40.51,53.98 C6.1
  Bottom 0.61: C6.1 39.52,55.41 C5.1 39.62,55.88 v43.5,55.88 40.32,59.06 37.78,59.06 C8.1 34.29,58.03 v34.29,58.1 32.7,58.1 32.07,57.47 32.07,55.11 33.52,53.66 | 33.52,53.66 v33.34,53.66 | 33.52,53.66 C7.1
  Bottom 0.813: v22.54,10.79 29.53,17.78 40.96,17.78 46.99,23.81 v46.99,40.01 46.99,45.52 v41.02,51.49 C6.1 | v49.85,40.01 61.28,40.01 | JP2.1 JP2.3 JP2.5 JP2.7 JP2.9 JP2.11 JP2.13 JP2.15 JP2.17 JP2.19 JP2.21 JP2.23 | JP2.23 JP2.25 JP2.27 JP2.29 JP2.31 JP2.33 JP2.35 JP2.37 JP2.39 JP2.41 JP2.43 JP2.45 JP2.47 | JP2.47 JP2.23 | 61.28,40.01 63.5,40.01 65.09,41.59 v65.09,62.55 65.09,73.34 64.14,74.3 JP2.47 | 61.28,40.01 SV1.2 | JP7.1 6.03,6.67 6.99,7.62 10.16,7.62 11.11,6.67 JP7.3
(copper drawn outside any net)
  shapes: Top circle x1

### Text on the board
Top: HEXA- CONTROL V1.0 by Christian Peters, 2011 | - | + | S | DA | . | CL | . | . | . | GND | . | . | . | . | 1 | RX | TX | K | F | TXD | ISP | GND | VCC | 7 | 6 | 5 | 4 | 3 | 2 | 1 | 0 | RXD | GND | ANT | . | RESET | POWER | 1 GND | 2 VCC | 3 GND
